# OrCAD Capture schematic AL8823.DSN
size Custom; title: AL8823, MR16 SINGLE BOOST LED CONTROLLER; rev: 1.0; note: DS39232 Rev. 1 - 2
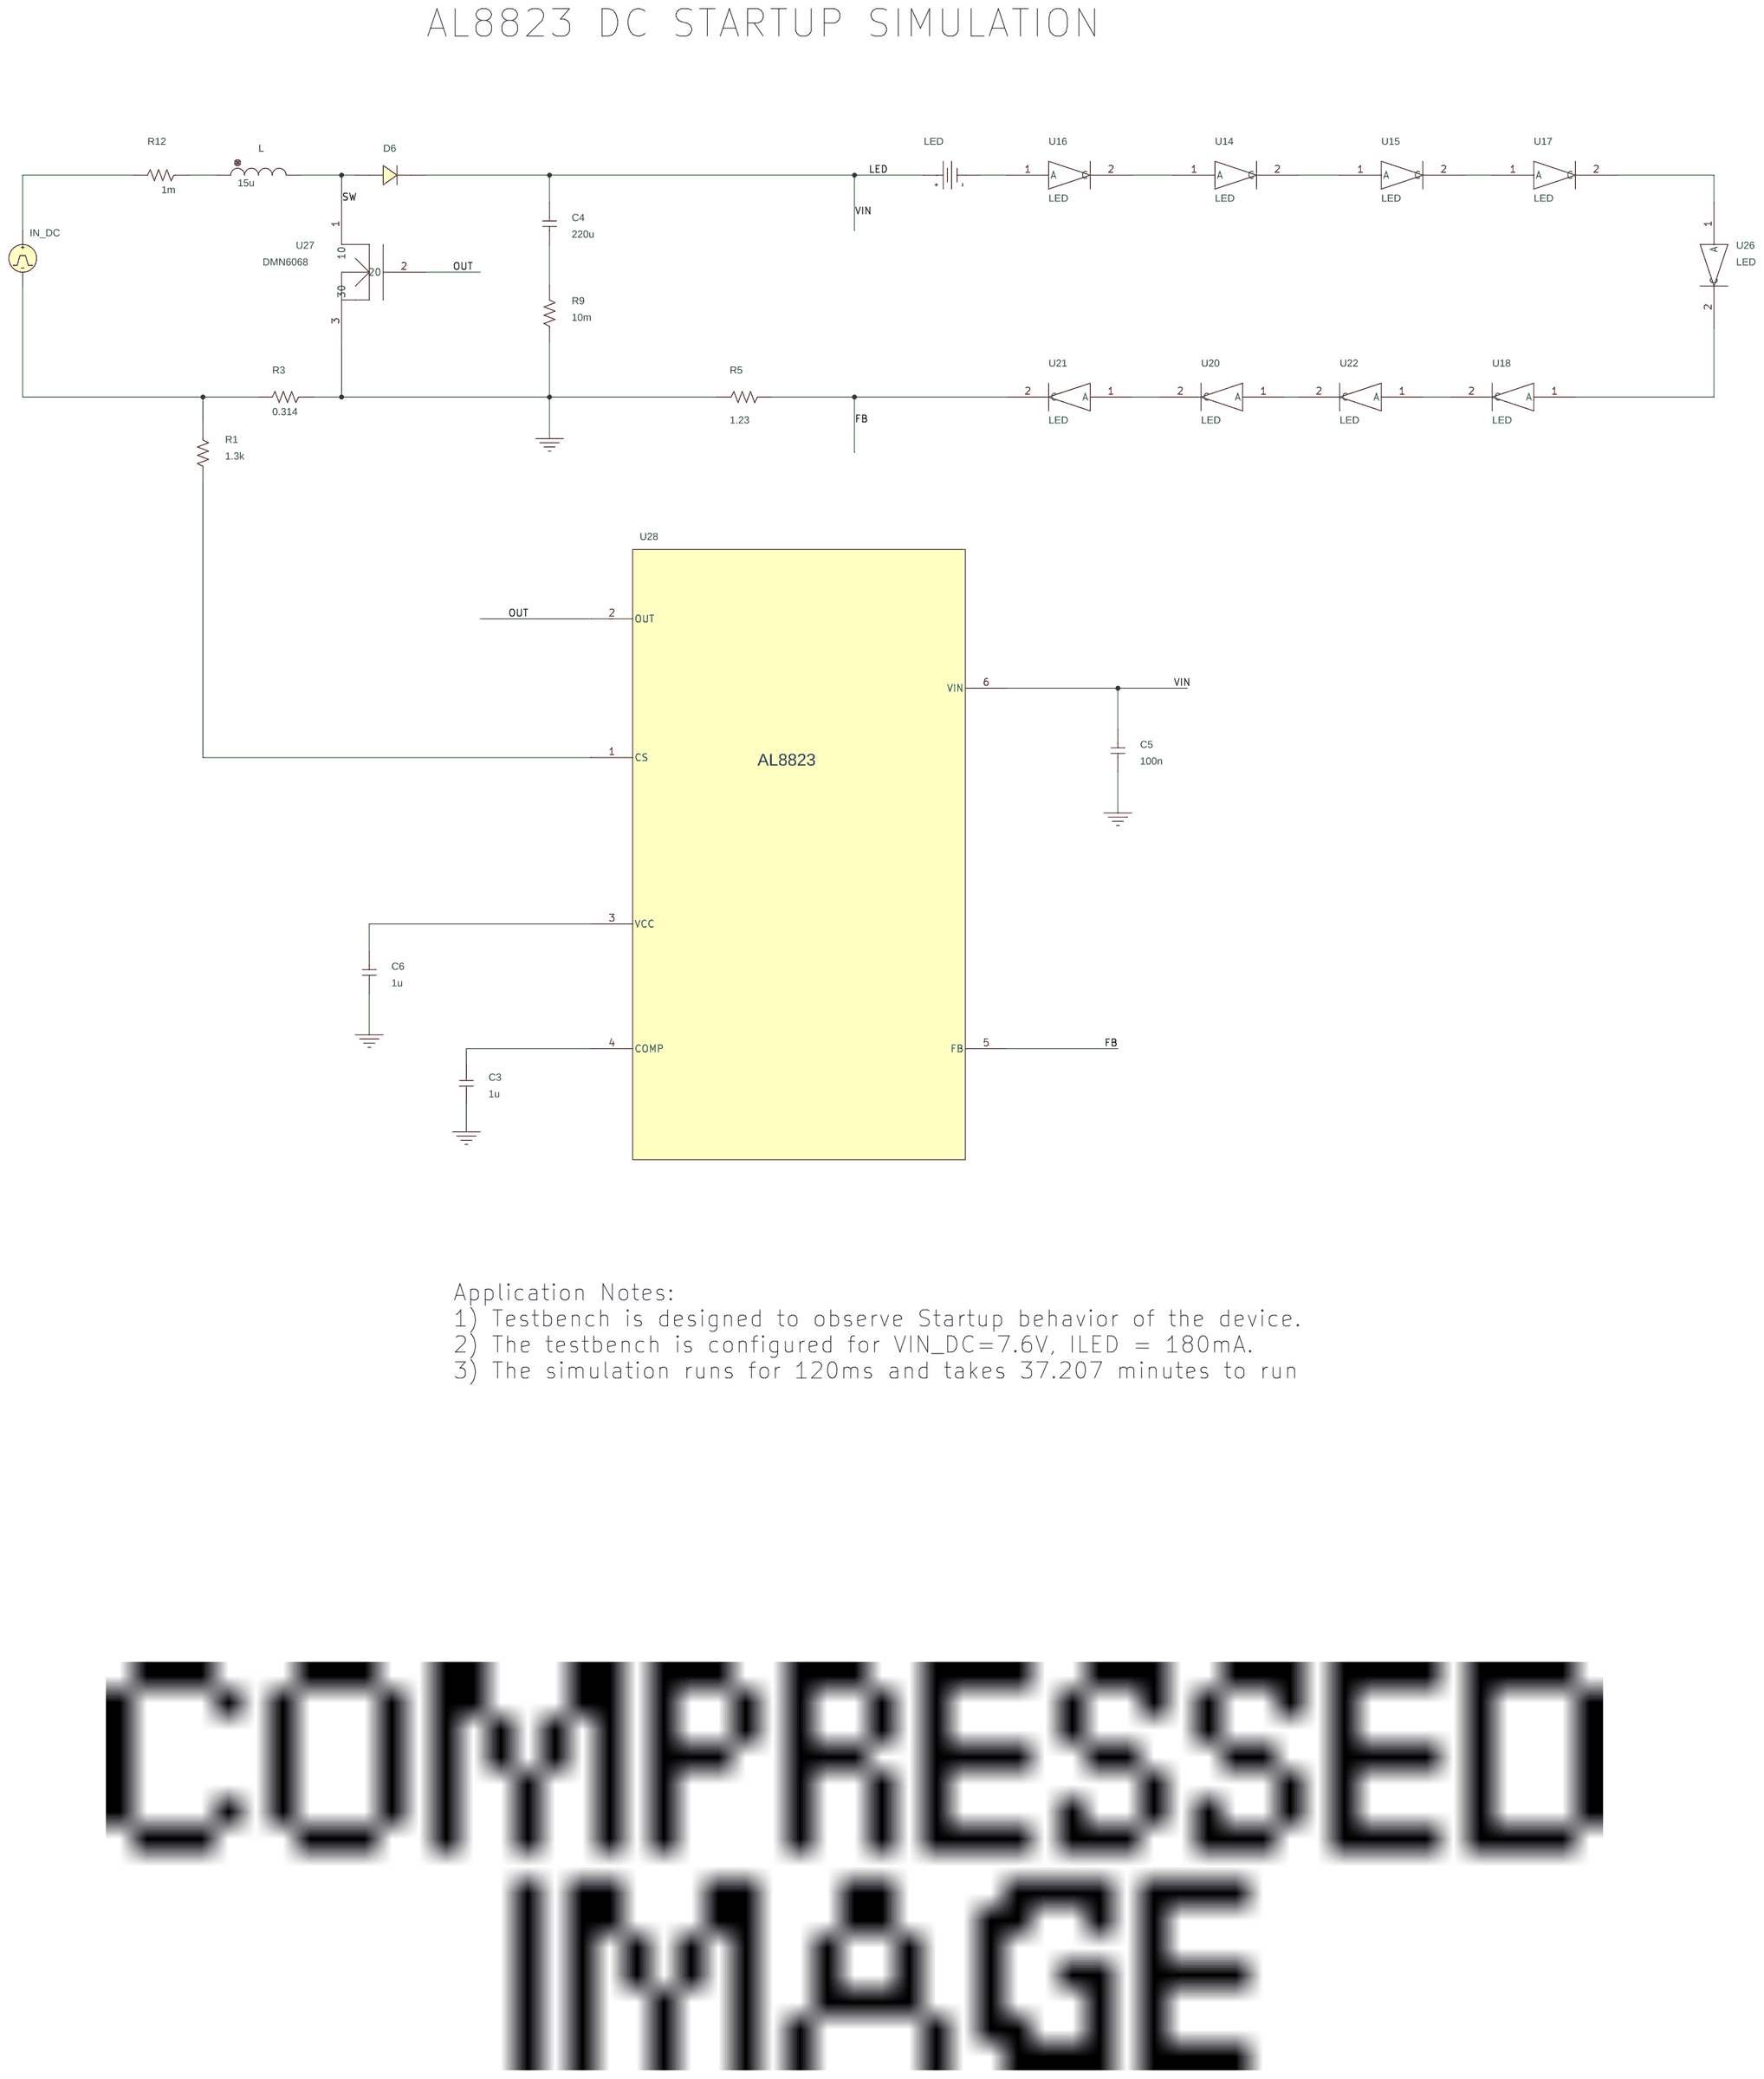
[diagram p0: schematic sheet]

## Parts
C3  1u  [RAD/CK05]
C4  220u  [RAD/CK05]
C5  100n  [RAD/CK05]
C6  1u  [RAD/CK05]
D6  DI_B240A  [DO41]
IN_DC  VPULSE
L  15u  [DISC/.350x.175/LS.200x.100/.034]
LED  VDC
R1  1.3k  [AX/RC05]
R3  0.314  [AX/RC05]
R5  1.23  [AX/RC05]
R9  10m  [AX/RC05]
R12  1m  [AX/RC05]
U14  LED
U15  LED
U16  LED
U17  LED
U18  LED
U20  LED
U21  LED
U22  LED
U26  LED
U27  DMN6068
U28  AL8823

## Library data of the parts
C3-C6 = C: IC: 0
D6 = DI_B240A
IN_DC = VPULSE: AC: 0; AppProp: Pulse$Voltage$0$-1; DC: 0; PER: 1.0000e+9; PW: 1.0000e+9; TD: 0; TF: 10m; TR: 10m; V1: 0; V2: 7.6
L = L: IC: 0
LED = VDC
R1 R3 R5 R9 R12 = R
U14-U18 U20-U22 U26 = LED_0
U27 = DMN6068_0
U28 = AL8823_0

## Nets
0: C3.1 C5.1 C6.1 R3.1 R5.1 R9.1 U27.3(30)
FB: R5.2 U21.2(C) U28.5(FB)
LED: C4.2 C5.2 D6.1(C) LED.0(+) U28.6(VIN)
OUT: U27.2(20) U28.2(OUT)
SW: D6.2(A) L.2 U27.1(10)
N30410: U14.2(C) U15.1(A)
N30416: U14.1(A) U16.2(C)
N30422: U17.2(C) U26.1(A)
N30518: L.1 R12.1
N30536: U18.2(C) U22.1(A)
N30542: U18.1(A) U26.2(C)
N30548: U15.2(C) U17.1(A)
N30710: IN_DC.2(-) R1.1 R3.2
N30742: C4.1 R9.2
N30926: U20.2(C) U21.1(A)
N30932: U20.1(A) U22.2(C)
N30944: IN_DC.1(+) R12.2
N30964: R1.2 U28.1(CS)
N31558: LED.1(-) U16.1(A)
N31874: C3.2 U28.4(COMP)
N31897: C6.2 U28.3(VCC)

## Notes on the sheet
- AL8823 DC STARTUP SIMULATION
- Application Notes:
  1) Testbench is designed to observe Startup behavior of the device.
  2) The testbench is configured for VIN_DC=7.6V, ILED = 180mA.
  3) The simulation runs for 120ms and takes 37.207 minutes to run
